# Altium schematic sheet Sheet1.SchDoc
size A4
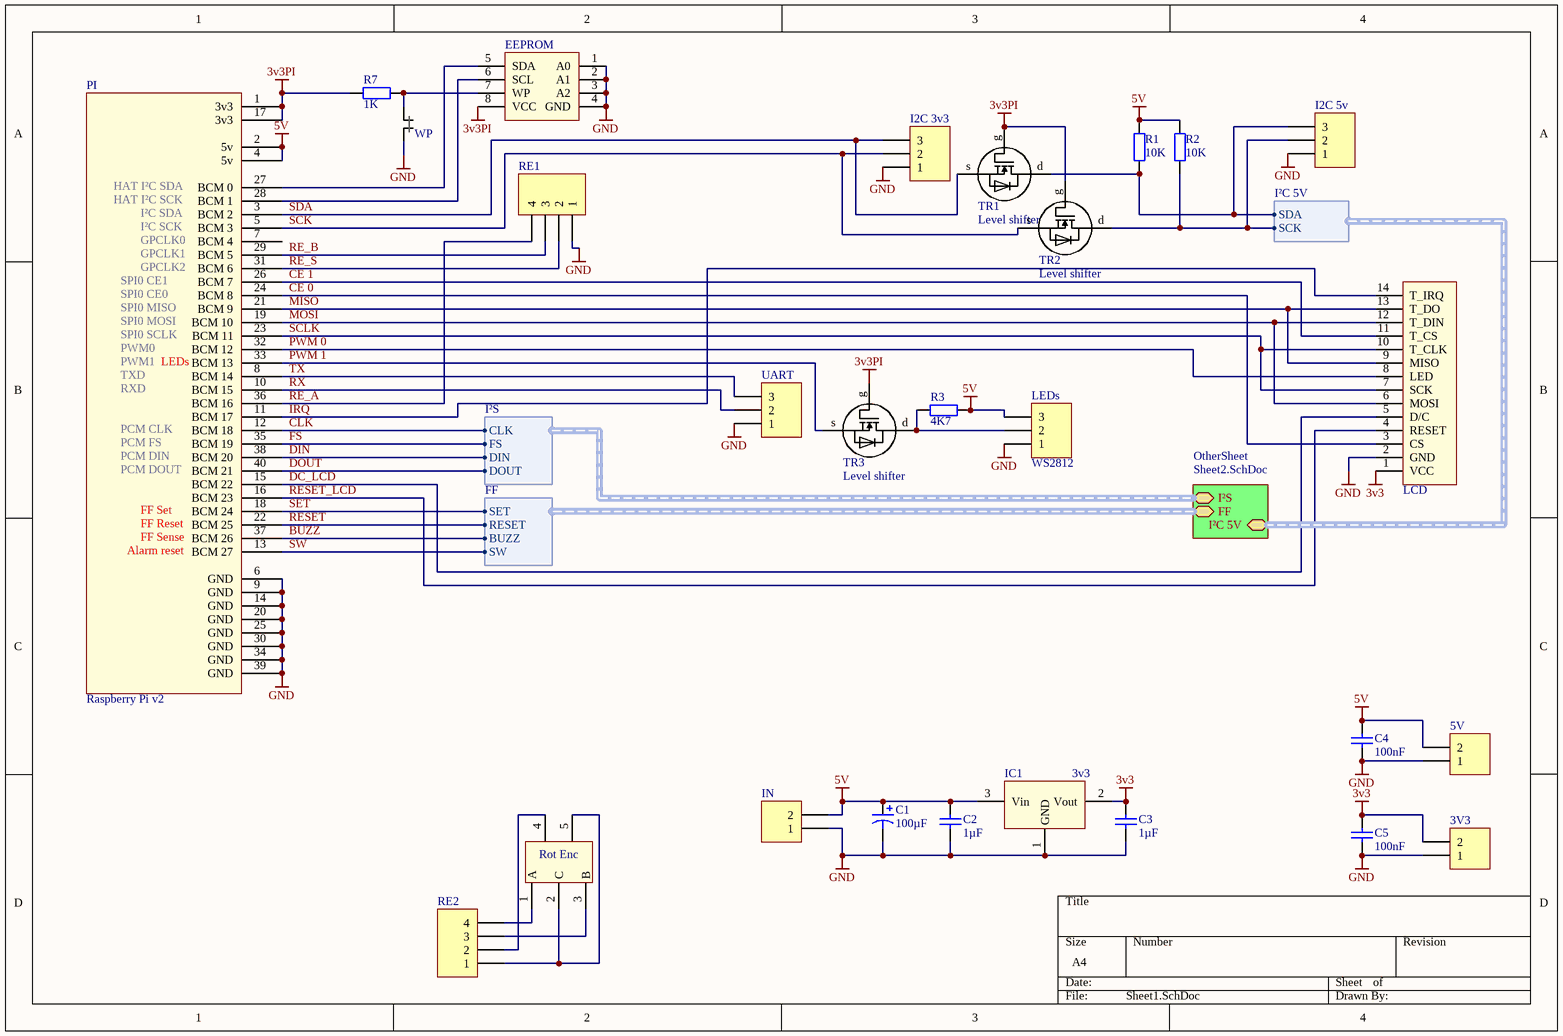
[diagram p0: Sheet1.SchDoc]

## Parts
3V3  (no value)  [HDR1X2]
5V  (no value)  [HDR1X2]
C1  value 100µF  [SMD cap 6x5]
C2  value 1µF  [C0805]
C3  value 1µF  [C0805]
C4  value 100nF  [C0805]
C5  value 100nF  [C0805]
EEPROM  I²C SERIAL EEPROM  [SOIC-8]  (value not drawn)
I2C_3v3  (no value)  [HDR1X3]
I2C_5v  (no value)  [HDR1X3]
IC1  3v3  [SOT-23A]
IN  (no value)  [HDR1X2]
LCD  TJCTM24024-SPI  (value not drawn)
LEDs  WS2812  [HDR1X3]
PI  Raspberry Pi v2  [HDR2x10]
R1  value 10K  [C1206]
R2  value 10K  [C1206]
R3  value 4K7  [C1206]
R7  value 1K  [C1206]
RE  (no value)  [EC11E-WP]
RE1  RotaryEncoder  [HDR1X4]  (value not drawn)
RE2  RotaryEncoder  [HDR1X4]  (value not drawn)
TR1  Level shifter  [SOT-23A]
TR2  Level shifter  [SOT-23A]
TR3  Level shifter  [SOT-23A]
UART  (no value)  [HDR1X3]
WP  Jumper  [HDR1X2]  (value not drawn)

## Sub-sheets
OtherSheet = Sheet2.SchDoc: FF (harness FF), I²S (harness I²S), I²C 5V (harness I²C 5V)

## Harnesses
I²S: CLK, FS, DIN, DOUT
I²C 5V: SDA, SCK
FF: SET, RESET, BUZZ, SW

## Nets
3v3: 3V3.2 C3.2 C5.1 IC1.2(Vout) LCD.1(VCC)
3v3PI: EEPROM.8(VCC) PI.1(3v3) PI.17(3v3) R7.2 TR1.g TR2.g TR3.g
5V: 5V.2 C1.1 C2.2 C4.2 IC1.3(Vin) IN.2 LEDs.3 PI.2(5v) PI.4(5v) R1.2 R2.2 R3.1
GND: 3V3.1 5V.1 C1.2 C2.1 C3.1 C4.1 C5.2 EEPROM.1(A0) EEPROM.2(A1) EEPROM.3(A2) EEPROM.4(GND) I2C_3v3.1 I2C_5v.1 IC1.1(GND) IN.1 LCD.2(GND) LEDs.1 PI.6(GND) PI.9(GND) PI.14(GND) PI.20(GND) PI.25(GND) PI.30(GND) PI.34(GND) PI.39(GND) RE1.1 UART.1 WP.1
BUZZ: PI.37(BCM_26) ; sheet OtherSheet/FF.BUZZ
CE 0: LCD.3(CS) PI.24(BCM_8)
CE 1: LCD.11(T_CS) PI.26(BCM_7)
CLK: PI.12(BCM_18) ; sheet OtherSheet/I²S.CLK
DC_LCD: LCD.5(D/C) PI.15(BCM_22)
DIN: PI.38(BCM_20) ; sheet OtherSheet/I²S.DIN
DOUT: PI.40(BCM_21) ; sheet OtherSheet/I²S.DOUT
FS: PI.35(BCM_19) ; sheet OtherSheet/I²S.FS
IRQ: LCD.14(T_IRQ) PI.11(BCM_17)
MISO: LCD.9(MISO) LCD.13(T_DO) PI.21(BCM_9)
MOSI: LCD.6(MOSI) LCD.12(T_DIN) PI.19(BCM_10)
PWM 0: LCD.8(LED) PI.32(BCM_12)
PWM 1: PI.33(BCM_13) TR3.s
RE_A: PI.36(BCM_16) RE1.4
RE_B: PI.29(BCM_5) RE1.3
RE_S: PI.31(BCM_6) RE1.2
RESET: PI.22(BCM_25) ; sheet OtherSheet/FF.RESET
RESET_LCD: LCD.4(RESET) PI.16(BCM_23)
RX: PI.10(BCM_15) UART.2
SCK: I2C_3v3.2 PI.5(BCM_3) TR2.s
SCLK: LCD.7(SCK) LCD.10(T_CLK) PI.23(BCM_11)
SDA: I2C_3v3.3 PI.3(BCM_2) TR1.s
SET: PI.18(BCM_24) ; sheet OtherSheet/FF.SET
SW: PI.13(BCM_27) ; sheet OtherSheet/FF.SW
TX: PI.8(BCM_14) UART.3
NetEEPROM_5: EEPROM.5(SDA) PI.27(BCM_0)
NetEEPROM_6: EEPROM.6(SCL) PI.28(BCM_1)
NetEEPROM_7: EEPROM.7(WP) R7.1 WP.2
NetI2C_5v_2: I2C_5v.2 R2.1 TR2.d ; sheet OtherSheet/I²C 5V.SCK
NetI2C_5v_3: I2C_5v.3 R1.1 TR1.d ; sheet OtherSheet/I²C 5V.SDA
NetLEDs_2: LEDs.2 R3.2 TR3.d
NetRE_1: RE.1(A) RE2.4
NetRE_2: RE.2(C) RE.5(F) RE2.1
NetRE_3: RE.3(B) RE2.3
NetRE_4: RE.4(E) RE2.2

Not connected (* = marked no-connect by the designer): PI 7(BCM_4)

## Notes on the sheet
- LEDs
- FF Set
- (near PI) Alarm reset
- (near PI) FF Sense
- (near PI) FF Reset

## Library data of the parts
3V3 5V IN = Header 2: Header, 2-Pin
C1 = Cap Pol1: Polarized Capacitor (Radial)
C2-C5 = Cap: Capacitor
I2C_3v3 I2C_5v LEDs UART = Header 3: Header, 3-Pin
IC1 = MCP1703: Power regulator
LCD = TJCTM24024-SPI: LCD module
PI = RaspberryPiV2: Raspberry Pi v2 Header
R1-R3 R7 = Res2: Resistor
RE = RotaryEncoder
RE1 RE2 = Header 4: Header, 4-Pin
TR1-TR3 = AN10441: pin to pad: d>3 g>1 s>2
